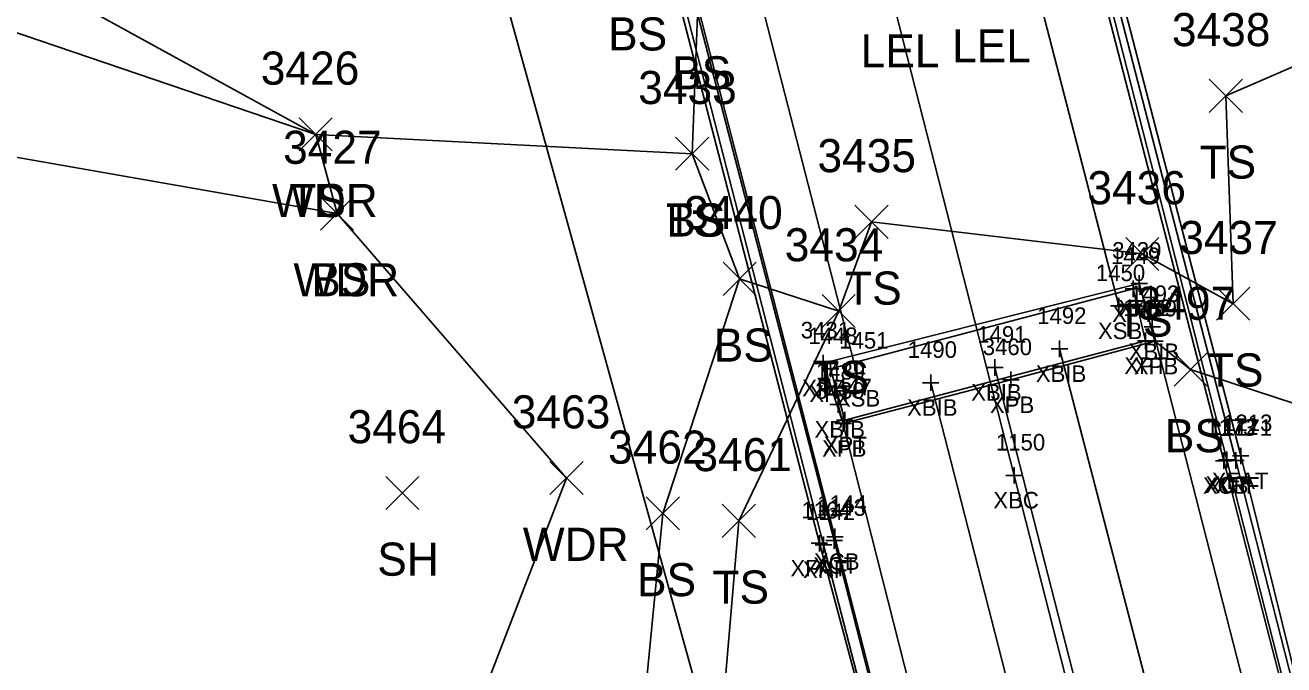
# Model space of a CAD drawing. Extents: x 1601151 to 1602912, y 499508 to 501770.
# Drawn here: x 1601546.4 to 1601622.4, y 500580.6 to 500619.2 of the extents above; entities that cross this region are included whole.
import ezdxf

# ---------------------------------------------------------------- set-up
doc = ezdxf.new("R2010")
doc.units = 0
for name, color, linetype in [('B_A', 7, 'Continuous'), ('B_I', 7, 'Continuous'), ('B_TIC', 7, 'Continuous'), ('BB', 7, 'Continuous'), ('BDC', 7, 'Continuous'), ('BELB', 7, 'Continuous'), ('BF', 7, 'Continuous'), ('BR', 7, 'Continuous'), ('BSUBM', 7, 'Continuous'), ('L_A', 7, 'Continuous'), ('L_I', 7, 'Continuous'), ('L_TIC', 7, 'Continuous'), ('LAWA', 7, 'Continuous'), ('LELB', 7, 'Continuous'), ('UCO', 7, 'Continuous')]:
    doc.layers.add(name, color=color, linetype=linetype)

msp = doc.modelspace()

# ---------------------------------------------------------------- linework, layer by layer
at = {"layer": 'B_TIC'}
for p, q in [((1601613.303, 500603.302), (1601613.379, 500603.302)), ((1601613.664, 500603.626), (1601613.739, 500603.626)), ((1601612.433, 500602.27), (1601612.509, 500602.27)), ((1601614.451, 500601.006), (1601614.527, 500601.006)), ((1601614.046, 500600.165), (1601614.122, 500600.165)), ((1601614.046, 500600.165), (1601614.122, 500600.165)), ((1601614.601, 500600.137), (1601614.677, 500600.137)), ((1601608.846, 500599.683), (1601608.922, 500599.683)), ((1601594.573, 500598.811), (1601594.648, 500598.811)), ((1601595.022, 500598.469), (1601595.098, 500598.469)), ((1601604.943, 500598.553), (1601605.019, 500598.553)), ((1601596.608, 500598.195), (1601596.684, 500598.195)), ((1601601.069, 500597.638), (1601601.145, 500597.638)), ((1601605.908, 500597.803), (1601605.983, 500597.803)), ((1601595.483, 500596.326), (1601595.559, 500596.326)), ((1601595.89, 500595.371), (1601595.966, 500595.371)), ((1601595.89, 500595.371), (1601595.966, 500595.371)), ((1601595.776, 500595.163), (1601595.852, 500595.163)), ((1601619.787, 500593.212), (1601619.863, 500593.212)), ((1601619.787, 500593.212), (1601619.863, 500593.212)), ((1601618.765, 500592.927), (1601618.841, 500592.927)), ((1601618.943, 500592.981), (1601619.019, 500592.981)), ((1601619.489, 500592.933), (1601619.565, 500592.933)), ((1601606.112, 500592.04), (1601606.188, 500592.04)), ((1601594.345, 500587.938), (1601594.421, 500587.938)), ((1601594.601, 500587.839), (1601594.677, 500587.839)), ((1601595.244, 500588.098), (1601595.32, 500588.098)), ((1601595.288, 500588.334), (1601595.364, 500588.334))]:
    msp.add_line(p, q, dxfattribs=at)
for points in [[(1601613.3, 500602.802), (1601613.3, 500603.802)], [(1601613.66, 500603.126), (1601613.66, 500604.126)], [(1601612.8, 500603.302), (1601613.8, 500603.302)], [(1601613.16, 500603.626), (1601614.16, 500603.626)], [(1601611.93, 500602.27), (1601612.93, 500602.27)], [(1601612.43, 500601.77), (1601612.43, 500602.77)], [(1601614.448, 500600.506), (1601614.448, 500601.506)], [(1601613.948, 500601.006), (1601614.948, 500601.006)], [(1601614.043, 500599.665), (1601614.043, 500600.665)], [(1601614.043, 500599.665), (1601614.043, 500600.665)], [(1601608.843, 500599.183), (1601608.843, 500600.183)], [(1601613.543, 500600.165), (1601614.543, 500600.165)], [(1601613.543, 500600.165), (1601614.543, 500600.165)], [(1601614.098, 500600.137), (1601615.098, 500600.137)], [(1601614.598, 500599.637), (1601614.598, 500600.637)], [(1601594.569, 500598.311), (1601594.569, 500599.311)], [(1601608.343, 500599.683), (1601609.343, 500599.683)], [(1601594.069, 500598.811), (1601595.069, 500598.811)], [(1601594.519, 500598.469), (1601595.519, 500598.469)], [(1601595.019, 500597.969), (1601595.019, 500598.969)], [(1601596.605, 500597.695), (1601596.605, 500598.695)], [(1601604.44, 500598.553), (1601605.44, 500598.553)], [(1601604.94, 500598.053), (1601604.94, 500599.053)], [(1601596.105, 500598.195), (1601597.105, 500598.195)], [(1601600.566, 500597.638), (1601601.566, 500597.638)], [(1601601.066, 500597.138), (1601601.066, 500598.138)], [(1601605.404, 500597.803), (1601606.404, 500597.803)], [(1601605.904, 500597.303), (1601605.904, 500598.303)], [(1601594.98, 500596.326), (1601595.98, 500596.326)], [(1601595.48, 500595.826), (1601595.48, 500596.826)], [(1601595.387, 500595.371), (1601596.387, 500595.371)], [(1601595.387, 500595.371), (1601596.387, 500595.371)], [(1601595.773, 500594.663), (1601595.773, 500595.663)], [(1601595.887, 500594.871), (1601595.887, 500595.871)], [(1601595.887, 500594.871), (1601595.887, 500595.871)], [(1601595.273, 500595.163), (1601596.273, 500595.163)], [(1601618.762, 500592.427), (1601618.762, 500593.427)], [(1601618.94, 500592.481), (1601618.94, 500593.481)], [(1601619.284, 500593.212), (1601620.284, 500593.212)], [(1601619.284, 500593.212), (1601620.284, 500593.212)], [(1601619.486, 500592.433), (1601619.486, 500593.433)], [(1601619.784, 500592.712), (1601619.784, 500593.712)], [(1601619.784, 500592.712), (1601619.784, 500593.712)], [(1601606.109, 500591.54), (1601606.109, 500592.54)], [(1601618.262, 500592.927), (1601619.262, 500592.927)], [(1601618.44, 500592.981), (1601619.44, 500592.981)], [(1601618.986, 500592.933), (1601619.986, 500592.933)], [(1601605.609, 500592.04), (1601606.609, 500592.04)], [(1601595.241, 500587.598), (1601595.241, 500588.598)], [(1601595.285, 500587.834), (1601595.285, 500588.834)], [(1601593.842, 500587.938), (1601594.842, 500587.938)], [(1601594.098, 500587.839), (1601595.098, 500587.839)], [(1601594.342, 500587.438), (1601594.342, 500588.438)], [(1601594.598, 500587.339), (1601594.598, 500588.339)], [(1601594.741, 500588.098), (1601595.741, 500588.098)], [(1601594.785, 500588.334), (1601595.785, 500588.334)]]:
    msp.add_lwpolyline(points, dxfattribs=at)
at = {"layer": 'BB'}
for points in [[(1601612.43, 500602.27), (1601552.33, 500834.638)], [(1601596.605, 500598.195), (1601536.682, 500830.877)], [(1601623.807, 500564.489), (1601614.448, 500601.006)], [(1601618.381, 500562.936), (1601608.843, 500599.683)], [(1601614.33, 500561.836), (1601604.94, 500598.553)], [(1601610.48, 500560.951), (1601601.066, 500597.638)], [(1601604.841, 500559.444), (1601595.48, 500596.326)]]:
    msp.add_lwpolyline(points, dxfattribs=at)
at = {"layer": 'BDC'}
for points in [[(1601626.62, 500562.484), (1601618.762, 500592.927), (1601608.069, 500634.25), (1601598.914, 500669.817), (1601586.174, 500719.227), (1601573.535, 500768.43), (1601563.157, 500808.618), (1601554.18, 500843.361), (1601545.696, 500876.636)], [(1601627.365, 500562.647), (1601626.817, 500562.743), (1601626.575, 500563.06), (1601618.94, 500592.981), (1601608.354, 500634.47), (1601599.142, 500669.932), (1601586.408, 500719.217), (1601573.699, 500768.593), (1601563.408, 500808.684), (1601554.3, 500843.382), (1601545.843, 500876.671)], [(1601521.711, 500869.959), (1601522.401, 500870.191), (1601530.668, 500838.288), (1601539.742, 500803.087), (1601549.8, 500763.941), (1601562.902, 500713.198), (1601575.298, 500665.088), (1601584.682, 500628.799), (1601595.241, 500588.098), (1601603.293, 500556.622), (1601602.827, 500556.326)], [(1601522.54, 500870.251), (1601530.887, 500838.161), (1601539.773, 500803.176), (1601550.059, 500763.65), (1601563.09, 500713.388), (1601575.504, 500665.097), (1601584.832, 500628.831), (1601595.285, 500588.334), (1601603.432, 500556.591), (1601602.763, 500556.075)]]:
    msp.add_lwpolyline(points, dxfattribs=at)
at = {"layer": 'BELB'}
msp.add_lwpolyline([(1601614.122, 500560.679), (1601606.109, 500592.04), (1601595.825, 500632.34), (1601585.652, 500672.123), (1601574.355, 500716.245), (1601561.498, 500765.241), (1601551.327, 500804.521), (1601542.34, 500839.856), (1601533.48, 500873.114)], dxfattribs=at)
at = {"layer": 'BF'}
for points in [[(1601546.596, 500876.467), (1601555.117, 500843.825), (1601564.25, 500808.582), (1601574.552, 500768.924), (1601587.26, 500719.439), (1601599.8, 500670.488), (1601609.07, 500634.571), (1601619.784, 500593.212)], [(1601521.711, 500869.959), (1601529.926, 500837.537), (1601538.825, 500802.891), (1601549.015, 500763.542), (1601561.986, 500712.939), (1601574.422, 500664.924), (1601583.827, 500628.557), (1601594.342, 500587.938), (1601602.827, 500556.326)], [(1601627.365, 500562.647), (1601619.784, 500593.212)]]:
    msp.add_lwpolyline(points, dxfattribs=at)
at = {"layer": 'BR'}
for points in [[(1601626.891, 500563.91), (1601619.486, 500592.933), (1601608.823, 500634.178), (1601599.631, 500670.204), (1601586.939, 500719.228), (1601574.289, 500768.594), (1601563.976, 500808.593), (1601554.991, 500843.345), (1601546.615, 500875.695)], [(1601521.915, 500869.371), (1601530.025, 500838.058), (1601539.084, 500802.864), (1601549.326, 500763.869), (1601562.422, 500713.041), (1601574.564, 500665.146), (1601584.098, 500628.637), (1601594.598, 500587.839), (1601602.424, 500557.542)]]:
    msp.add_lwpolyline(points, dxfattribs=at)
at = {"layer": 'BSUBM'}
for points in [[(1601595.773, 500595.163), (1601594.569, 500598.811), (1601613.66, 500603.626), (1601614.598, 500600.137), (1601605.904, 500597.803), (1601595.773, 500595.163)], [(1601595.887, 500595.371), (1601595.019, 500598.469), (1601613.3, 500603.302), (1601614.043, 500600.165)], [(1601595.887, 500595.371), (1601614.043, 500600.165)]]:
    msp.add_lwpolyline(points, dxfattribs=at)
at = {"layer": 'L_TIC'}
for points in [[(1601617.889, 500613.96), (1601619.889, 500615.96)], [(1601619.889, 500613.96), (1601617.889, 500615.96)], [(1601562.929, 500611.634), (1601564.929, 500613.634)], [(1601564.929, 500611.634), (1601562.929, 500613.634)], [(1601562.929, 500611.634), (1601564.929, 500613.634)], [(1601564.929, 500611.634), (1601562.929, 500613.634)], [(1601585.664, 500610.463), (1601587.664, 500612.463)], [(1601587.664, 500610.463), (1601585.664, 500612.463)], [(1601585.664, 500610.463), (1601587.664, 500612.463)], [(1601587.664, 500610.463), (1601585.664, 500612.463)], [(1601564.22, 500606.854), (1601566.22, 500608.854)], [(1601566.22, 500606.854), (1601564.22, 500608.854)], [(1601564.22, 500606.854), (1601566.22, 500608.854)], [(1601566.22, 500606.854), (1601564.22, 500608.854)], [(1601596.489, 500606.35), (1601598.489, 500608.35)], [(1601598.489, 500606.35), (1601596.489, 500608.35)], [(1601612.844, 500604.412), (1601614.844, 500606.412)], [(1601614.844, 500604.412), (1601612.844, 500606.412)], [(1601588.525, 500602.909), (1601590.525, 500604.909)], [(1601590.525, 500602.909), (1601588.525, 500604.909)], [(1601594.511, 500600.966), (1601596.511, 500602.966)], [(1601596.511, 500600.966), (1601594.511, 500602.966)], [(1601594.511, 500600.966), (1601596.511, 500602.966)], [(1601596.511, 500600.966), (1601594.511, 500602.966)], [(1601618.332, 500601.406), (1601620.332, 500603.406)], [(1601620.332, 500601.406), (1601618.332, 500603.406)], [(1601615.763, 500597.436), (1601617.763, 500599.436)], [(1601617.763, 500597.436), (1601615.763, 500599.436)], [(1601578.076, 500590.876), (1601580.076, 500592.876)], [(1601580.076, 500590.876), (1601578.076, 500592.876)], [(1601568.162, 500589.98), (1601570.162, 500591.98)], [(1601570.162, 500589.98), (1601568.162, 500591.98)], [(1601583.892, 500588.745), (1601585.892, 500590.745)], [(1601585.892, 500588.745), (1601583.892, 500590.745)], [(1601588.477, 500588.294), (1601590.477, 500590.294)], [(1601590.477, 500588.294), (1601588.477, 500590.294)]]:
    msp.add_lwpolyline(points, dxfattribs=at)
at = {"layer": 'LAWA'}
msp.add_lwpolyline([(1601302.554, 500689.494), (1601363.582, 500662.81), (1601380.112, 500655.57), (1601400.842, 500652.587), (1601450.949, 500643.85), (1601476.799, 500629.175), (1601478.067, 500629.171), (1601496.832, 500636.997), (1601499.443, 500638.013), (1601508.973, 500634.749), (1601512.572, 500627.469), (1601537.323, 500627.233), (1601563.929, 500612.634), (1601565.22, 500607.854), (1601579.076, 500591.876), (1601571.602, 500572.536), (1601570.483, 500566.05)], dxfattribs=at)
at = {"layer": 'LELB'}
for points in [[(1601499.443, 500638.013), (1601500.401, 500627.932), (1601510.136, 500624.067), (1601515.788, 500620.238), (1601542.385, 500619.961), (1601563.929, 500612.634), (1601586.664, 500611.463)], [(1601515.788, 500620.238), (1601541.102, 500612.088), (1601565.22, 500607.854)], [(1601587.012, 500620.349), (1601586.664, 500611.463), (1601589.525, 500603.909), (1601584.892, 500589.745), (1601583.232, 500572.746), (1601582.008, 500556.938), (1601586.093, 500551.377), (1601586.32, 500550.708)], [(1601595.511, 500601.966), (1601597.489, 500607.35), (1601613.844, 500605.412), (1601619.332, 500602.406), (1601618.889, 500614.96), (1601626.124, 500618.106), (1601628.385, 500608.444), (1601639.426, 500596.608), (1601678.531, 500593.269), (1601684.776, 500593.468), (1601700.016, 500593.106), (1601710.484, 500590.716), (1601727.344, 500588.151), (1601745.421, 500586.504), (1601758.447, 500586.976)], [(1601589.525, 500603.909), (1601595.511, 500601.966)], [(1601595.511, 500601.966), (1601589.477, 500589.294), (1601587.852, 500570.121), (1601586.567, 500558.707), (1601586.093, 500551.377)], [(1601614.598, 500600.137), (1601616.763, 500598.436)], [(1601616.763, 500598.436), (1601640.736, 500590.561), (1601657.838, 500583.361), (1601670.086, 500571.938), (1601661.389, 500568.714), (1601659.319, 500568.082)]]:
    msp.add_lwpolyline(points, dxfattribs=at)
at = {"layer": 'UCO'}
msp.add_lwpolyline([(1601595.966, 500546.616), (1601489.931, 500928.889)], dxfattribs=at)

# ---------------------------------------------------------------- texts
at = {"layer": 'B_A'}
for s, p in [('XPT', (1601612.02, 500601.302)), ('XPB', (1601612.397, 500601.626)), ('XSB', (1601611.166, 500600.27)), ('XBIB', (1601613.019, 500599.006)), ('XPT', (1601612.763, 500598.165)), ('XPT', (1601612.763, 500598.165)), ('XPB', (1601613.334, 500598.137)), ('XBIB', (1601607.414, 500597.683)), ('XPB', (1601593.305, 500596.811)), ('XPT', (1601593.739, 500596.469)), ('XSB', (1601595.341, 500596.195)), ('XBIB', (1601603.511, 500596.553)), ('XBIB', (1601599.637, 500595.638)), ('XPB', (1601604.64, 500595.803)), ('XBIB', (1601594.051, 500594.326)), ('XPB', (1601594.509, 500593.163)), ('XPT', (1601594.607, 500593.371)), ('XPT', (1601594.607, 500593.371)), ('XCB', (1601617.498, 500590.927)), ('XCT', (1601617.66, 500590.981)), ('XFAT', (1601618.04, 500591.212)), ('XFAT', (1601618.04, 500591.212)), ('XRF', (1601618.246, 500590.933)), ('XBC', (1601604.845, 500590.04)), ('XCT', (1601593.961, 500586.098)), ('XCB', (1601594.021, 500586.334)), ('XFAT', (1601592.598, 500585.938)), ('XRF', (1601593.358, 500585.839))]:
    msp.add_text(s, height=1, dxfattribs=at).set_placement(p)
at = {"layer": 'B_I'}
for s, p in [('3439', (1601612.027, 500605.126)), ('1449', (1601611.95, 500604.802)), ('1450', (1601611.04, 500603.77)), ('1493', (1601613.102, 500602.506)), ('1492', (1601607.497, 500601.183)), ('1452', (1601612.697, 500601.665)), ('1452', (1601612.697, 500601.665)), ('3459', (1601612.964, 500601.637)), ('3431', (1601593.223, 500600.311)), ('1448', (1601593.673, 500599.969)), ('1451', (1601595.542, 500599.695)), ('1491', (1601603.877, 500600.053)), ('1490', (1601599.676, 500599.138)), ('3460', (1601604.207, 500599.303)), ('1489', (1601594.13, 500597.826)), ('3430', (1601594.099, 500596.663)), ('1447', (1601594.541, 500596.871)), ('1447', (1601594.541, 500596.871)), ('1173', (1601617.699, 500594.427)), ('1172', (1601617.877, 500594.481)), ('1171', (1601618.707, 500594.433)), ('1213', (1601618.721, 500594.712)), ('1213', (1601618.721, 500594.712)), ('1150', (1601605.003, 500593.54)), ('1144', (1601594.222, 500589.834)), ('1164', (1601593.256, 500589.438)), ('1142', (1601593.535, 500589.339)), ('1143', (1601594.178, 500589.598))]:
    msp.add_text(s, height=1, dxfattribs=at).set_placement(p)
at = {"layer": 'L_A'}
for s, p in [('BS', (1601581.585, 500617.699)), ('LEL', (1601602.357, 500616.986)), ('LEL', (1601596.832, 500616.678)), ('BS', (1601585.453, 500615.349)), ('BS', (1601585.453, 500615.349)), ('TS', (1601617.299, 500609.96)), ('WDR', (1601561.291, 500607.634)), ('TS', (1601562.339, 500607.634)), ('TS', (1601585.074, 500606.463)), ('BS', (1601585.105, 500606.463)), ('WDR', (1601562.583, 500602.854)), ('BS', (1601563.661, 500602.854)), ('TS', (1601595.898, 500602.35)), ('TS', (1601612.253, 500600.412)), ('BS', (1601587.966, 500598.909)), ('TS', (1601617.742, 500597.406)), ('TS', (1601593.921, 500596.966)), ('TS', (1601593.921, 500596.966)), ('BS', (1601615.204, 500593.436)), ('WDR', (1601576.438, 500586.876)), ('SH', (1601567.65, 500585.98)), ('BS', (1601583.333, 500584.745)), ('TS', (1601587.886, 500584.294))]:
    msp.add_text(s, height=2, dxfattribs=at).set_placement(p)
at = {"layer": 'L_I'}
for s, p in [('3438', (1601615.629, 500617.96)), ('3426', (1601560.614, 500615.634)), ('3426', (1601560.614, 500615.634)), ('3433', (1601583.404, 500614.463)), ('3433', (1601583.404, 500614.463)), ('3427', (1601561.961, 500610.854)), ('3427', (1601561.961, 500610.854)), ('3435', (1601594.229, 500610.35)), ('3436', (1601610.529, 500608.412)), ('3440', (1601586.179, 500606.909)), ('3434', (1601592.252, 500604.966)), ('3434', (1601592.252, 500604.966)), ('3437', (1601616.073, 500605.406)), ('3497', (1601613.503, 500601.436)), ('3463', (1601575.769, 500594.876)), ('3464', (1601565.855, 500593.98)), ('3462', (1601581.585, 500592.745)), ('3461', (1601586.737, 500592.294))]:
    msp.add_text(s, height=2, dxfattribs=at).set_placement(p)

doc.saveas('drawing.dxf')
